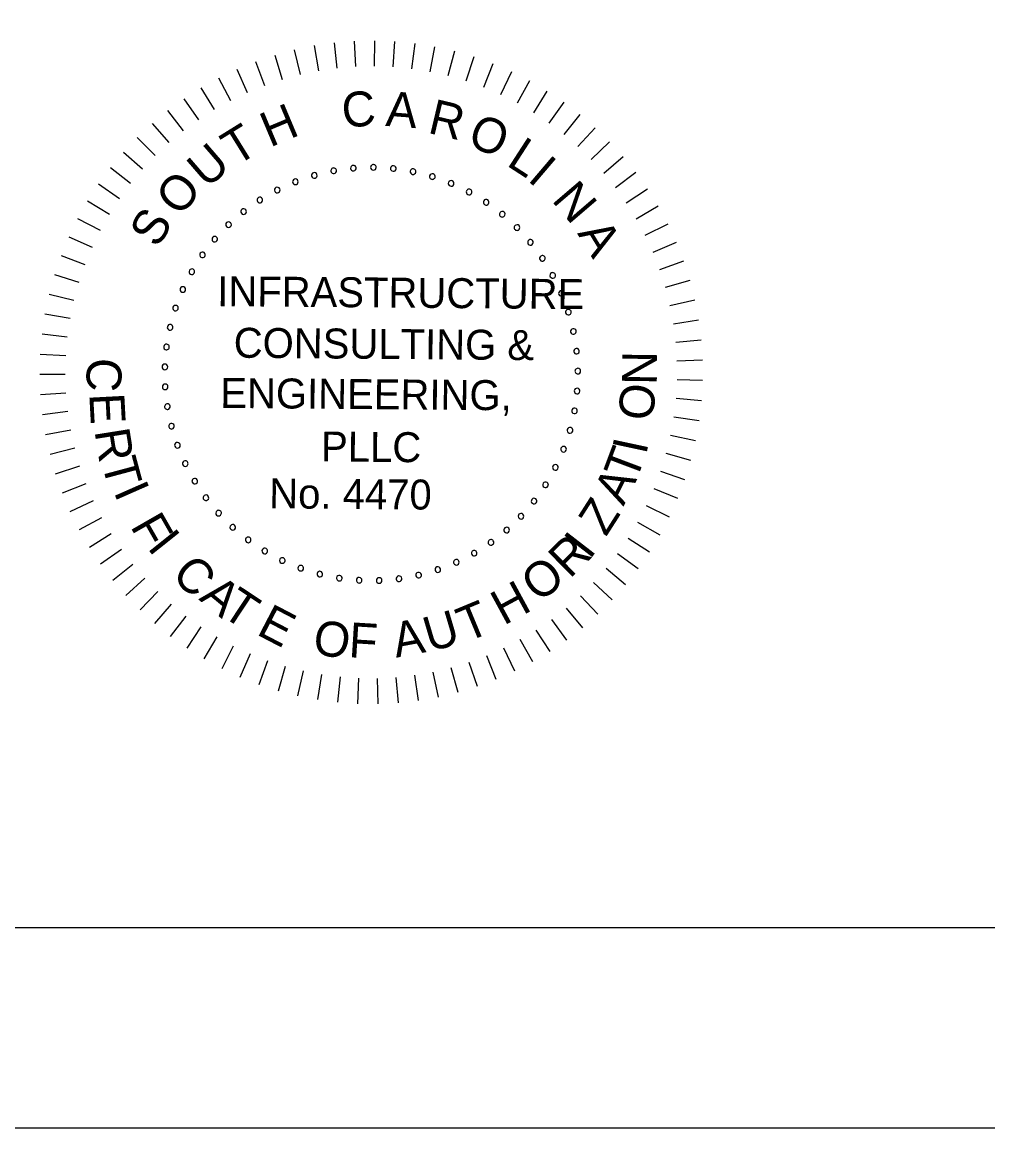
# Model space of a CAD drawing. Extents: x -133.1 to -97, y -1.7 to 20.3.
# Drawn here: x -107.68 to -105.268, y -1.691 to 1.069 of the extents above; entities that cross this region are included whole.
import ezdxf

# ---------------------------------------------------------------- set-up
doc = ezdxf.new("R2010")
doc.units = 0
for name, color, linetype in [('BR_BORDER LINES', 7, 'Continuous'), ('BR_TEXT', 7, 'Continuous'), ('Level 31', 7, 'Continuous')]:
    doc.layers.add(name, color=color, linetype=linetype)

msp = doc.modelspace()

# ---------------------------------------------------------------- linework, layer by layer
at = {"layer": 'BR_BORDER LINES'}
msp.add_line((-131.3076, -1.191), (-97.6416, -1.191), dxfattribs=at)
at = {"layer": 'BR_TEXT'}
for p, q in [((-106.8509, 1.0213), (-106.8476, 0.9578)), ((-106.8005, 1.0224), (-106.801, 0.9587)), ((-107.0007, 0.9998), (-106.9858, 0.9379)), ((-106.9512, 1.01), (-106.9401, 0.9473)), ((-106.9012, 1.0172), (-106.894, 0.9539)), ((-106.75, 1.0204), (-106.7544, 0.9569)), ((-106.6998, 1.0153), (-106.7081, 0.9522)), ((-106.65, 1.0071), (-106.6621, 0.9446)), ((-106.6007, 0.996), (-106.6166, 0.9343)), ((-107.0972, 0.9704), (-107.0749, 0.9107)), ((-107.0494, 0.9866), (-107.0308, 0.9257)), ((-106.5523, 0.9818), (-106.5719, 0.9213)), ((-107.1439, 0.9513), (-107.1181, 0.8932)), ((-106.5048, 0.9648), (-106.528, 0.9055)), ((-106.4584, 0.9448), (-106.4852, 0.8871)), ((-107.1895, 0.9295), (-107.1601, 0.873)), ((-106.4133, 0.9221), (-106.4436, 0.8661)), ((-107.2335, 0.9049), (-107.2008, 0.8503)), ((-106.3697, 0.8967), (-106.4034, 0.8426)), ((-107.276, 0.8776), (-107.24, 0.8251)), ((-106.3277, 0.8686), (-106.3646, 0.8167)), ((-107.3168, 0.8478), (-107.2776, 0.7976)), ((-106.2875, 0.8381), (-106.3275, 0.7885)), ((-107.3557, 0.8156), (-107.3135, 0.7679)), ((-106.2493, 0.8051), (-106.2922, 0.7581)), ((-107.3925, 0.7811), (-107.3475, 0.736)), ((-106.2131, 0.7699), (-106.2588, 0.7256)), ((-107.4272, 0.7444), (-107.3795, 0.7022)), ((-106.1791, 0.7326), (-106.2275, 0.6911)), ((-107.4595, 0.7056), (-107.4094, 0.6664)), ((-106.1475, 0.6932), (-106.1983, 0.6548)), ((-107.4895, 0.665), (-107.437, 0.6289)), ((-106.1184, 0.652), (-106.1714, 0.6167)), ((-107.5169, 0.6226), (-107.4623, 0.5897)), ((-106.0918, 0.6091), (-106.1469, 0.5771)), ((-107.5416, 0.5786), (-107.4852, 0.5491)), ((-106.0679, 0.5646), (-106.1248, 0.5361)), ((-107.5637, 0.5332), (-107.5055, 0.5072)), ((-106.0467, 0.5188), (-106.1052, 0.4938)), ((-107.5829, 0.4865), (-107.5233, 0.4641)), ((-106.0283, 0.4718), (-106.0883, 0.4504)), ((-107.5992, 0.4387), (-107.5384, 0.42)), ((-106.0129, 0.4237), (-106.0741, 0.406)), ((-107.6126, 0.3901), (-107.5507, 0.3751)), ((-106.0004, 0.3748), (-106.0625, 0.3608)), ((-107.623, 0.3407), (-107.5604, 0.3295)), ((-105.9909, 0.3252), (-106.0538, 0.3151)), ((-107.6304, 0.2907), (-107.5672, 0.2834)), ((-105.9845, 0.2751), (-106.0479, 0.2689)), ((-107.6348, 0.2404), (-107.5712, 0.237)), ((-105.9811, 0.2247), (-106.0448, 0.2224)), ((-107.636, 0.19), (-107.5723, 0.1904)), ((-105.9809, 0.1743), (-106.0445, 0.1758)), ((-107.6342, 0.1395), (-107.5706, 0.1438)), ((-105.9836, 0.1239), (-106.0471, 0.1292)), ((-107.6293, 0.0893), (-107.5661, 0.0974)), ((-105.9895, 0.0737), (-106.0525, 0.0829)), ((-107.6213, 0.0394), (-107.5588, 0.0514)), ((-105.9984, 0.024), (-106.0607, 0.0371)), ((-107.6103, -0.0099), (-107.5487, 0.0059)), ((-106.0103, -0.025), (-106.0717, -0.0082)), ((-107.5964, -0.0584), (-107.5358, -0.0388)), ((-106.0252, -0.0733), (-106.0855, -0.0527)), ((-107.5795, -0.106), (-107.5202, -0.0828)), ((-106.043, -0.1205), (-106.1019, -0.0963)), ((-107.5597, -0.1524), (-107.5019, -0.1256)), ((-106.0636, -0.1666), (-106.1209, -0.1389)), ((-107.5371, -0.1976), (-107.4811, -0.1673)), ((-106.087, -0.2113), (-106.1426, -0.1802)), ((-107.5119, -0.2413), (-107.4578, -0.2077)), ((-106.1131, -0.2545), (-106.1667, -0.22)), ((-107.484, -0.2834), (-107.4321, -0.2465)), ((-106.1418, -0.2961), (-106.1931, -0.2584)), ((-107.4536, -0.3237), (-107.404, -0.2837)), ((-106.173, -0.3358), (-106.2219, -0.2951)), ((-107.4208, -0.362), (-107.3737, -0.3191)), ((-106.2065, -0.3735), (-106.2529, -0.3299)), ((-107.3857, -0.3983), (-107.3413, -0.3527)), ((-107.3485, -0.4324), (-107.307, -0.3841)), ((-106.2423, -0.4092), (-106.2859, -0.3628)), ((-107.3092, -0.4642), (-107.2708, -0.4135)), ((-106.2801, -0.4426), (-106.3208, -0.3936)), ((-107.2681, -0.4935), (-107.2328, -0.4405)), ((-106.32, -0.4736), (-106.3576, -0.4222)), ((-107.2253, -0.5203), (-107.1933, -0.4652)), ((-106.3616, -0.5021), (-106.3961, -0.4485)), ((-107.1809, -0.5444), (-107.1523, -0.4875)), ((-106.4498, -0.5513), (-106.4774, -0.4939)), ((-106.4049, -0.528), (-106.436, -0.4725)), ((-107.1352, -0.5657), (-107.1101, -0.5072)), ((-107.0882, -0.5842), (-107.0668, -0.5243)), ((-106.4959, -0.5718), (-106.52, -0.5128)), ((-107.0402, -0.5998), (-107.0225, -0.5387)), ((-106.9913, -0.6125), (-106.9773, -0.5504)), ((-106.5915, -0.6041), (-106.6083, -0.5427)), ((-106.5432, -0.5894), (-106.5637, -0.5291)), ((-106.9418, -0.6221), (-106.9316, -0.5593)), ((-106.8918, -0.6288), (-106.8854, -0.5654)), ((-106.8414, -0.6323), (-106.8389, -0.5687)), ((-106.7909, -0.6328), (-106.7923, -0.5691)), ((-106.7405, -0.6302), (-106.7458, -0.5667)), ((-106.6903, -0.6245), (-106.6995, -0.5615)), ((-106.6406, -0.6158), (-106.6536, -0.5535))]:
    msp.add_line(p, q, dxfattribs=at)
for centre, start, end in [((-106.9506, 0.6862), 16.1422, 196.1422), ((-106.9021, 0.6977), 10.6038, 190.6038), ((-106.9021, 0.6977), 190.6038, 10.6038), ((-106.8527, 0.7043), 5.0653, 185.0653), ((-106.8527, 0.7043), 185.0653, 5.0653), ((-106.8029, 0.7062), 359.5268, 179.5268), ((-106.8029, 0.7062), 179.5268, 359.5268), ((-106.7531, 0.7033), 173.9884, 353.9884), ((-106.7531, 0.7033), 353.9884, 173.9884), ((-106.7039, 0.6956), 168.4499, 348.4499), ((-106.7039, 0.6956), 348.4499, 168.4499), ((-106.6557, 0.6832), 342.9114, 162.9114), ((-106.9977, 0.6702), 21.6807, 201.6807), ((-106.9977, 0.6702), 201.6807, 21.6807), ((-106.9506, 0.6862), 196.1422, 16.1422), ((-106.6557, 0.6832), 162.9114, 342.9114), ((-106.6088, 0.6662), 157.373, 337.373), ((-106.6088, 0.6662), 337.373, 157.373), ((-107.0431, 0.6496), 27.2191, 207.2191), ((-107.0431, 0.6496), 207.2191, 27.2191), ((-106.5639, 0.6447), 151.8345, 331.8345), ((-106.5639, 0.6447), 331.8345, 151.8345), ((-107.0864, 0.6248), 32.7576, 212.7576), ((-107.0864, 0.6248), 212.7576, 32.7576), ((-106.5212, 0.619), 146.2961, 326.2961), ((-106.5212, 0.619), 326.2961, 146.2961), ((-107.127, 0.5959), 38.2961, 218.2961), ((-107.127, 0.5959), 218.2961, 38.2961), ((-106.4811, 0.5893), 140.7576, 320.7576), ((-106.4811, 0.5893), 320.7576, 140.7576), ((-107.1646, 0.5633), 43.8345, 223.8345), ((-107.1646, 0.5633), 223.8345, 43.8345), ((-106.4442, 0.5559), 135.2191, 315.2191), ((-106.4442, 0.5559), 315.2191, 135.2191), ((-107.1989, 0.5271), 49.373, 229.373), ((-107.1989, 0.5271), 229.373, 49.373), ((-106.4106, 0.5191), 129.6807, 309.6807), ((-106.4106, 0.5191), 309.6807, 129.6807), ((-107.2296, 0.4879), 54.9114, 234.9114), ((-107.2296, 0.4879), 234.9114, 54.9114), ((-106.3808, 0.4792), 124.1422, 304.1422), ((-106.3808, 0.4792), 304.1422, 124.1422), ((-107.2563, 0.4458), 60.4499, 240.4499), ((-107.2563, 0.4458), 240.4499, 60.4499), ((-106.3549, 0.4366), 118.6038, 298.6038), ((-106.3549, 0.4366), 298.6038, 118.6038), ((-107.2788, 0.4014), 65.9884, 245.9884), ((-107.2788, 0.4014), 245.9884, 65.9884), ((-106.3333, 0.3917), 113.0653, 293.0653), ((-106.3333, 0.3917), 293.0653, 113.0653), ((-107.297, 0.3549), 71.5268, 251.5268), ((-107.297, 0.3549), 251.5268, 71.5268), ((-106.3161, 0.3449), 107.5268, 287.5268), ((-106.3161, 0.3449), 287.5268, 107.5268), ((-107.3106, 0.307), 77.0653, 257.0653), ((-107.3106, 0.307), 257.0653, 77.0653), ((-106.3035, 0.2967), 281.9884, 101.9884), ((-106.3035, 0.2967), 101.9884, 281.9884), ((-107.3195, 0.258), 82.6038, 262.6038), ((-107.3195, 0.258), 262.6038, 82.6038), ((-106.2956, 0.2475), 96.4499, 276.4499), ((-106.2956, 0.2475), 276.4499, 96.4499), ((-107.3236, 0.2083), 88.1422, 268.1422), ((-107.3236, 0.2083), 268.1422, 88.1422), ((-106.2925, 0.1977), 90.9114, 270.9114), ((-106.2925, 0.1977), 270.9114, 90.9114), ((-107.3229, 0.1585), 93.6807, 273.6807), ((-107.3229, 0.1585), 273.6807, 93.6807), ((-106.2942, 0.1479), 85.373, 265.373), ((-106.2942, 0.1479), 265.373, 85.373), ((-107.3174, 0.109), 99.2191, 279.2191), ((-107.3174, 0.109), 279.2191, 99.2191), ((-106.3007, 0.0985), 79.8345, 259.8345), ((-106.3007, 0.0985), 259.8345, 79.8345), ((-107.3071, 0.0602), 104.7576, 284.7576), ((-107.3071, 0.0602), 284.7576, 104.7576), ((-106.312, 0.05), 74.2961, 254.2961), ((-106.312, 0.05), 254.2961, 74.2961), ((-107.2922, 0.0126), 110.2961, 290.2961), ((-107.2922, 0.0126), 290.2961, 110.2961), ((-106.3279, 0.0028), 68.7576, 248.7576), ((-106.3279, 0.0028), 248.7576, 68.7576), ((-107.2728, -0.0332), 115.8345, 295.8345), ((-107.2728, -0.0332), 295.8345, 115.8345), ((-106.3483, -0.0427), 63.2191, 243.2191), ((-106.3483, -0.0427), 243.2191, 63.2191), ((-107.249, -0.077), 121.373, 301.373), ((-107.249, -0.077), 301.373, 121.373), ((-106.3729, -0.086), 57.6807, 237.6807), ((-106.3729, -0.086), 237.6807, 57.6807), ((-107.2211, -0.1183), 126.9114, 306.9114), ((-107.2211, -0.1183), 306.9114, 126.9114), ((-106.4016, -0.1267), 52.1422, 232.1422), ((-106.4016, -0.1267), 232.1422, 52.1422), ((-107.1894, -0.1567), 132.4499, 312.4499), ((-107.1894, -0.1567), 312.4499, 132.4499), ((-106.4342, -0.1645), 46.6038, 226.6038), ((-106.4342, -0.1645), 226.6038, 46.6038), ((-107.1541, -0.1919), 137.9884, 317.9884), ((-107.1541, -0.1919), 317.9884, 137.9884), ((-106.4702, -0.1989), 41.0653, 221.0653), ((-107.1156, -0.2235), 143.5268, 323.5268), ((-107.1156, -0.2235), 323.5268, 143.5268), ((-106.4702, -0.1989), 221.0653, 41.0653), ((-107.0742, -0.2512), 149.0653, 329.0653), ((-107.0742, -0.2512), 329.0653, 149.0653), ((-106.5093, -0.2297), 35.5268, 215.5268), ((-106.5093, -0.2297), 215.5268, 35.5268), ((-107.0303, -0.2749), 154.6038, 334.6038), ((-107.0303, -0.2749), 334.6038, 154.6038), ((-106.5957, -0.2793), 24.4499, 204.4499), ((-106.5513, -0.2566), 29.9884, 209.9884), ((-106.5513, -0.2566), 209.9884, 29.9884), ((-106.9843, -0.2941), 160.1422, 340.1422), ((-106.9843, -0.2941), 340.1422, 160.1422), ((-106.9367, -0.3089), 345.6807, 165.6807), ((-106.642, -0.2976), 18.9114, 198.9114), ((-106.642, -0.2976), 198.9114, 18.9114), ((-106.5957, -0.2793), 204.4499, 24.4499), ((-106.9367, -0.3089), 165.6807, 345.6807), ((-106.8879, -0.3189), 171.2191, 351.2191), ((-106.8879, -0.3189), 351.2191, 171.2191), ((-106.8384, -0.3242), 356.7576, 176.7576), ((-106.8384, -0.3242), 176.7576, 356.7576), ((-106.7885, -0.3248), 2.2961, 182.2961), ((-106.7885, -0.3248), 182.2961, 2.2961), ((-106.7389, -0.3205), 7.8345, 187.8345), ((-106.7389, -0.3205), 187.8345, 7.8345), ((-106.6899, -0.3114), 13.373, 193.373), ((-106.6899, -0.3114), 193.373, 13.373)]:
    msp.add_arc(centre, 0.00701, start, end, dxfattribs=at)
at = {"layer": 'Level 31'}
msp.add_lwpolyline([(-133.1409, -1.691), (-97.141, -1.691), (-97.141, 20.309), (-133.1409, 20.309)], close=True, dxfattribs=at)

# ---------------------------------------------------------------- texts
at = {"layer": 'BR_TEXT'}
for s, height, rotation, p in [('C', 0.0872, 4.7281, (-106.8784, 0.8048)), ('A', 0.0872, 355.6981, (-106.7739, 0.8098)), ('H', 0.0872, 22.7882, (-107.0612, 0.7554)), ('R', 0.0872, 346.6681, (-106.6696, 0.7928)), ('O', 0.0872, 337.638, (-106.5719, 0.763)), ('T', 0.0872, 31.8182, (-107.1461, 0.7078)), ('L', 0.0872, 327.108, (-106.4731, 0.7125)), ('U', 0.0872, 40.8482, (-107.2194, 0.6516)), ('I', 0.0872, 319.578, (-106.4205, 0.6747)), ('O', 0.0872, 49.8782, (-107.2864, 0.5806)), ('N', 0.0872, 310.548, (-106.3597, 0.6239)), ('S', 0.0872, 58.9083, (-107.3418, 0.5024)), ('A', 0.0872, 301.5179, (-106.2946, 0.5415)), ('INFRASTRUCTURE', 0.074771, 359.5268, (-107.1932, 0.3599)), ('CONSULTING &', 0.074771, 359.5268, (-107.1519, 0.2313)), ('C', 0.0872, 267.025, (-107.5168, 0.2325)), ('N', 0.0872, 89.2085, (-106.0953, 0.1628)), ('ENGINEERING,', 0.074771, 359.5268, (-107.1855, 0.1059)), ('O', 0.0872, 83.2085, (-106.1064, 0.0713)), ('E', 0.0872, 273.025, (-107.5124, 0.1409)), ('R', 0.0872, 279.025, (-107.4996, 0.0487)), ('PLLC', 0.07477, 359.5268, (-106.9338, -0.0277)), ('T', 0.0872, 69.3954, (-106.1476, -0.0805)), ('I', 0.0872, 77.9093, (-106.1219, -0.013)), ('T', 0.0872, 285.025, (-107.4822, -0.0301)), ('I', 0.0872, 293.7713, (-107.4525, -0.1032)), ('No. 4470', 0.07477, 359.5268, (-107.0633, -0.1446)), ('A', 0.0872, 63.3954, (-106.1784, -0.1408)), ('Z', 0.0872, 57.3954, (-106.2222, -0.2172)), ('F', 0.0872, 299.7713, (-107.4113, -0.1893)), ('I', 0.0872, 308.5268, (-107.3692, -0.2431)), ('R', 0.0872, 44.5268, (-106.3127, -0.3221)), ('I', 0.0872, 52.3339, (-106.2633, -0.2748)), ('C', 0.0872, 314.5268, (-107.3099, -0.3133)), ('O', 0.0872, 38.5268, (-106.3893, -0.3821)), ('A', 0.0872, 320.5268, (-107.2407, -0.3718)), ('H', 0.0872, 28.5268, (-106.4774, -0.4381)), ('T', 0.0872, 326.5268, (-107.1863, -0.4103)), ('E', 0.0872, 332.5268, (-107.0977, -0.4581)), ('T', 0.0872, 22.5268, (-106.5706, -0.4799)), ('U', 0.0872, 16.5268, (-106.6623, -0.5042)), ('O', 0.0872, 350.5268, (-106.9576, -0.507)), ('F', 0.0872, 356.5268, (-106.8661, -0.5161)), ('A', 0.0872, 10.5268, (-106.7462, -0.5177))]:
    msp.add_text(s, height=height, rotation=rotation, dxfattribs=at).set_placement(p)

doc.saveas('drawing.dxf')
